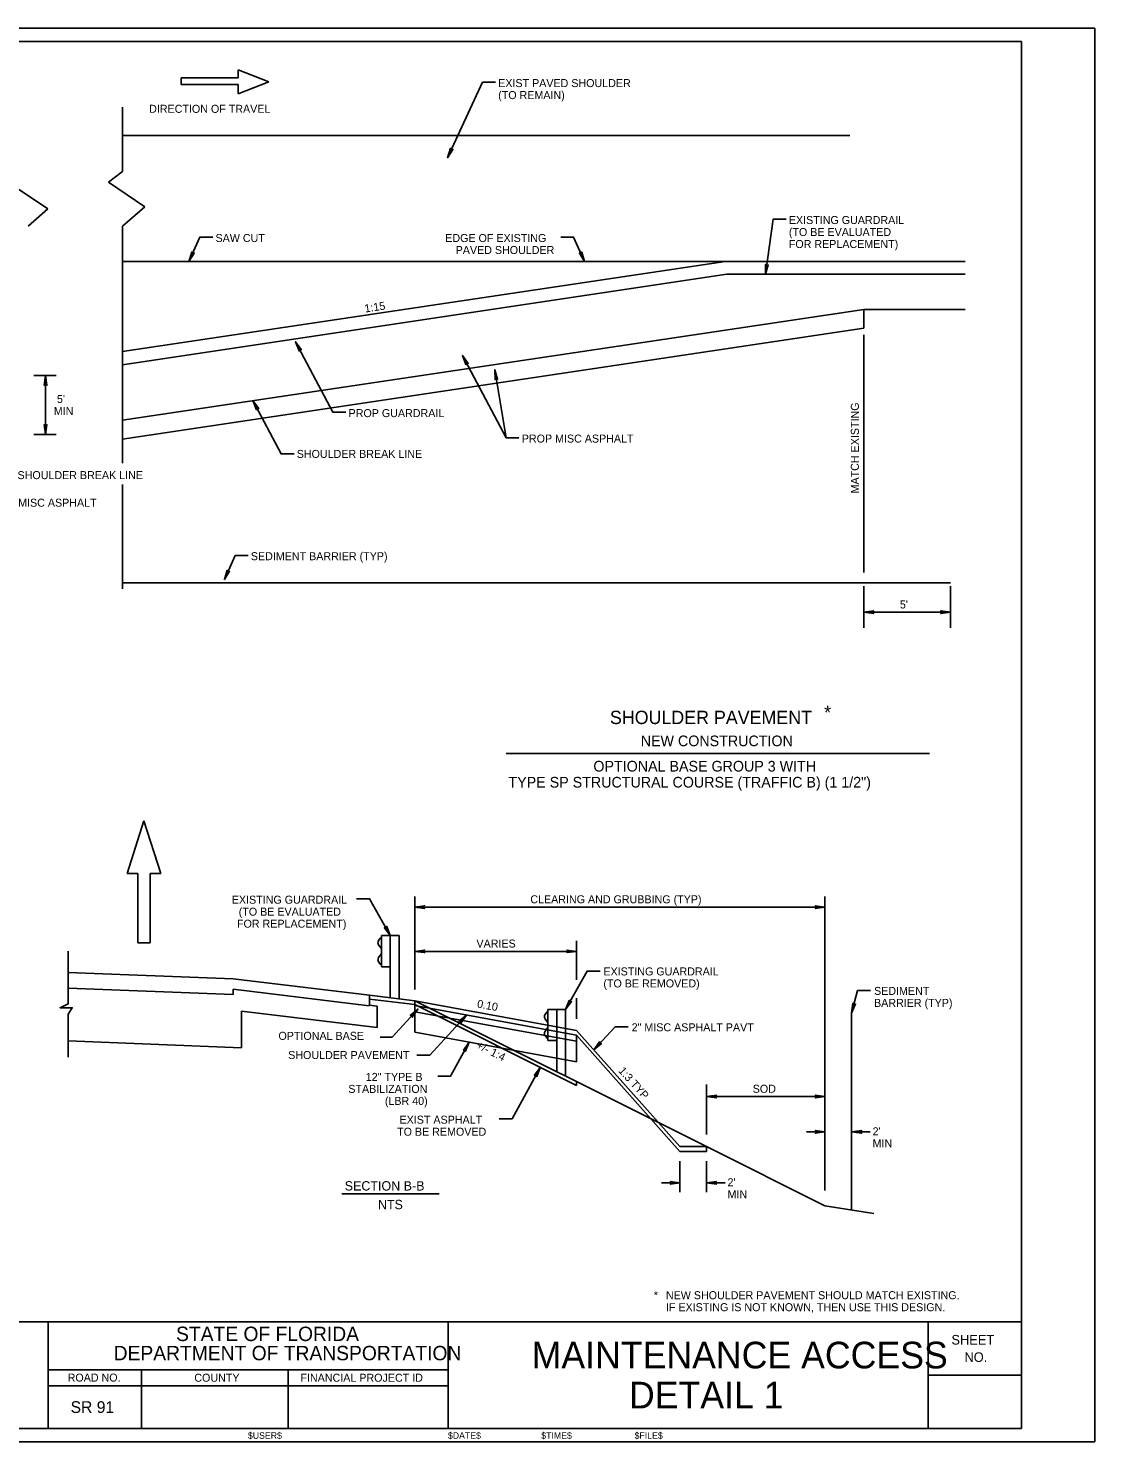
# Model space of a CAD drawing. Extents: x 96794 to 96959, y 32203 to 32309.
# Drawn here: x 96878.8 to 96958.8, y 32202.6 to 32308.6 of the extents above; entities that cross this region are included whole.
import ezdxf

# ---------------------------------------------------------------- set-up
doc = ezdxf.new("R2010")
doc.units = 0
for name, color, linetype in [('AsphaltMisc', 7, 'Continuous'), ('Base_ex', 7, 'Continuous'), ('BreakLine_dp', 7, 'Continuous'), ('DimLines_dp', 7, 'Continuous'), ('EOP', 7, 'Continuous'), ('GuardrailRt', 7, 'Continuous'), ('LeaderLine_dp', 7, 'Continuous'), ('Miscellaneous2', 7, 'Continuous'), ('PavtAsph_ep', 7, 'Continuous'), ('PlotBorder_dp', 7, 'Continuous'), ('SawCuts', 7, 'Continuous'), ('SheetBorder_dp', 7, 'Continuous'), ('SheetLines_dp', 7, 'Continuous'), ('SheetLinesMisc2_dp', 7, 'Continuous'), ('SiltFence', 7, 'Continuous'), ('Slopes_px', 7, 'Continuous'), ('TextMinor', 7, 'Continuous'), ('TextMisc', 7, 'Continuous'), ('TextTitle', 7, 'Continuous'), ('XSTypical_px', 7, 'Continuous')]:
    doc.layers.add(name, color=color, linetype=linetype)

msp = doc.modelspace()

# ---------------------------------------------------------------- linework, layer by layer
at = {"layer": 'AsphaltMisc'}
for p, q in [((96885.88, 32284.31), (96931.08, 32291.06)), ((96885.88, 32284.31), (96931.08, 32291.06)), ((96931.08, 32291.06), (96885.88, 32291.06)), ((96885.88, 32291.06), (96885.88, 32284.31)), ((96931.08, 32291.06), (96949.08, 32291.06)), ((96885.88, 32279.15), (96941.49, 32287.46)), ((96941.49, 32287.46), (96949.08, 32287.46))]:
    msp.add_line(p, q, dxfattribs=at)
at = {"layer": 'Base_ex'}
for p, q in [((96904.99, 32233.62), (96894.81, 32234.85)), ((96894.81, 32232.09), (96894.81, 32234.85)), ((96904.4, 32235.28), (96904.99, 32235.21)), ((96904.99, 32235.21), (96904.99, 32233.62)), ((96881.82, 32232.61), (96894.81, 32232.09))]:
    msp.add_line(p, q, dxfattribs=at)
at = {"layer": 'BreakLine_dp'}
msp.add_lwpolyline([(96881.82, 32239.35), (96881.82, 32235.4), (96881.2, 32235.1), (96882.12, 32235.1), (96881.81, 32234.61), (96881.81, 32231.4)], dxfattribs=at)
at = {"layer": 'DimLines_dp'}
for p, q in [((96885.88, 32302.63), (96885.88, 32297.81)), ((96884.83, 32297), (96885.88, 32297.81)), ((96880.29, 32295), (96877.56, 32296.84)), ((96887.56, 32295.16), (96884.83, 32297)), ((96885.88, 32293.7), (96887.56, 32295.16)), ((96878.82, 32293.72), (96880.29, 32295)), ((96885.88, 32293.7), (96885.88, 32275.94)), ((96941.49, 32267.74), (96941.49, 32285.55)), ((96879.24, 32282.51), (96880.92, 32282.51)), ((96880.12, 32282.51), (96880.12, 32278.09)), ((96879.24, 32278.09), (96880.92, 32278.09)), ((96885.88, 32274.34), (96885.88, 32266.52)), ((96941.49, 32263.58), (96941.49, 32266.7)), ((96947.98, 32263.58), (96947.98, 32266.7)), ((96947.98, 32264.76), (96941.49, 32264.76)), ((96907.81, 32236.47), (96907.81, 32243.45)), ((96938.57, 32221.4), (96938.57, 32243.45)), ((96907.81, 32242.65), (96938.57, 32242.65)), ((96919.94, 32237.19), (96919.94, 32240.12)), ((96907.81, 32239.32), (96919.94, 32239.32)), ((96919.94, 32234.26), (96919.94, 32235.82)), ((96929.69, 32225.59), (96929.69, 32229.33)), ((96929.69, 32228.44), (96938.57, 32228.44)), ((96937.18, 32225.79), (96938.57, 32225.79)), ((96937.18, 32225.79), (96938.57, 32225.79)), ((96941.97, 32225.79), (96940.57, 32225.79)), ((96941.97, 32225.79), (96940.57, 32225.79)), ((96927.69, 32221.26), (96927.69, 32223.58)), ((96929.69, 32221.26), (96929.69, 32223.58)), ((96926.3, 32221.97), (96927.69, 32221.97)), ((96926.3, 32221.97), (96927.69, 32221.97)), ((96931.09, 32221.97), (96929.69, 32221.97)), ((96931.09, 32221.97), (96929.69, 32221.97)), ((96902.34, 32221.14), (96909.64, 32221.14))]:
    msp.add_line(p, q, dxfattribs=at)
for points in [[(96880.12, 32281.98), (96880.21, 32281.78), (96880.12, 32282.51), (96880.02, 32281.78), (96880.12, 32281.98)], [(96880.12, 32278.62), (96880.21, 32278.83), (96880.12, 32278.09), (96880.02, 32278.83), (96880.12, 32278.62)], [(96942.02, 32264.76), (96942.23, 32264.86), (96941.49, 32264.76), (96942.23, 32264.66), (96942.02, 32264.76)], [(96947.45, 32264.76), (96947.25, 32264.86), (96947.98, 32264.76), (96947.25, 32264.66), (96947.45, 32264.76)], [(96908.34, 32242.65), (96908.54, 32242.55), (96907.81, 32242.65), (96908.54, 32242.75), (96908.34, 32242.65)], [(96938.04, 32242.65), (96937.84, 32242.75), (96938.57, 32242.65), (96937.84, 32242.55), (96938.04, 32242.65)], [(96908.34, 32239.32), (96908.54, 32239.42), (96907.81, 32239.32), (96908.54, 32239.23), (96908.34, 32239.32)], [(96919.41, 32239.32), (96919.21, 32239.42), (96919.94, 32239.32), (96919.21, 32239.23), (96919.41, 32239.32)], [(96930.22, 32228.44), (96930.43, 32228.53), (96929.69, 32228.44), (96930.43, 32228.34), (96930.22, 32228.44)], [(96938.04, 32228.44), (96937.84, 32228.53), (96938.57, 32228.44), (96937.84, 32228.34), (96938.04, 32228.44)], [(96938.04, 32225.79), (96937.84, 32225.69), (96938.57, 32225.79), (96937.84, 32225.88), (96938.04, 32225.79)], [(96938.04, 32225.79), (96937.84, 32225.88), (96938.57, 32225.79), (96937.84, 32225.69), (96938.04, 32225.79)], [(96941.1, 32225.79), (96941.31, 32225.69), (96940.57, 32225.79), (96941.31, 32225.88), (96941.1, 32225.79)], [(96941.1, 32225.79), (96941.31, 32225.88), (96940.57, 32225.79), (96941.31, 32225.69), (96941.1, 32225.79)], [(96927.16, 32221.97), (96926.96, 32221.87), (96927.69, 32221.97), (96926.96, 32222.06), (96927.16, 32221.97)], [(96927.16, 32221.97), (96926.96, 32222.06), (96927.69, 32221.97), (96926.96, 32221.87), (96927.16, 32221.97)], [(96930.22, 32221.97), (96930.43, 32221.87), (96929.69, 32221.97), (96930.43, 32222.06), (96930.22, 32221.97)], [(96930.22, 32221.97), (96930.43, 32222.06), (96929.69, 32221.97), (96930.43, 32221.87), (96930.22, 32221.97)]]:
    msp.add_lwpolyline(points, dxfattribs=at)
at = {"layer": 'EOP'}
for p, q in [((96890.28, 32304.83), (96894.57, 32304.83)), ((96890.28, 32304.83), (96890.28, 32304.33)), ((96894.57, 32304.83), (96894.57, 32305.44)), ((96894.57, 32305.44), (96896.87, 32304.54)), ((96894.57, 32304.33), (96890.28, 32304.33)), ((96894.57, 32303.64), (96896.87, 32304.54)), ((96894.57, 32303.64), (96894.57, 32304.33)), ((96885.88, 32300.52), (96940.43, 32300.52))]:
    msp.add_line(p, q, dxfattribs=at)
at = {"layer": 'GuardrailRt'}
for p, q in [((96885.88, 32283.32), (96931.22, 32290.1)), ((96931.22, 32290.1), (96949.08, 32290.1))]:
    msp.add_line(p, q, dxfattribs=at)
at = {"layer": 'LeaderLine_dp'}
for points in [[(96913.86, 32304.5), (96912.89, 32304.5), (96910.26, 32298.84)], [(96910.48, 32299.32), (96910.48, 32299.55), (96910.26, 32298.84), (96910.66, 32299.46), (96910.48, 32299.32)], [(96935.66, 32294.24), (96934.69, 32294.24), (96934.12, 32290.1)], [(96892.65, 32292.89), (96891.69, 32292.89), (96890.87, 32291.06)], [(96918.76, 32292.89), (96919.72, 32292.89), (96920.54, 32291.06)], [(96891.09, 32291.55), (96891.08, 32291.77), (96890.87, 32291.06), (96891.26, 32291.69), (96891.09, 32291.55)], [(96920.32, 32291.55), (96920.33, 32291.77), (96920.54, 32291.06), (96920.15, 32291.69), (96920.32, 32291.55)], [(96934.19, 32290.63), (96934.12, 32290.84), (96934.12, 32290.1), (96934.31, 32290.81), (96934.19, 32290.63)], [(96902.64, 32279.75), (96901.67, 32279.75), (96898.87, 32285.04)], [(96899.12, 32284.57), (96899.3, 32284.44), (96898.87, 32285.04), (96899.13, 32284.35), (96899.12, 32284.57)], [(96915.62, 32277.84), (96914.66, 32277.84), (96911.38, 32284.02)], [(96911.63, 32283.55), (96911.81, 32283.42), (96911.38, 32284.02), (96911.64, 32283.33), (96911.63, 32283.55)], [(96915.62, 32277.84), (96914.66, 32277.84), (96913.8, 32282.94)], [(96913.89, 32282.42), (96914.02, 32282.23), (96913.8, 32282.94), (96913.83, 32282.2), (96913.89, 32282.42)], [(96898.75, 32276.63), (96897.78, 32276.63), (96895.67, 32280.63)], [(96895.92, 32280.16), (96896.1, 32280.03), (96895.67, 32280.63), (96895.93, 32279.94), (96895.92, 32280.16)], [(96895.31, 32269.02), (96894.34, 32269.02), (96893.53, 32267.2)], [(96893.74, 32267.68), (96893.74, 32267.91), (96893.53, 32267.2), (96893.91, 32267.83), (96893.74, 32267.68)], [(96903.44, 32243.26), (96904.41, 32243.26), (96905.97, 32240.51)], [(96905.71, 32240.97), (96905.7, 32241.19), (96905.97, 32240.51), (96905.53, 32241.1), (96905.71, 32240.97)], [(96921.7, 32237.85), (96920.73, 32237.85), (96919.12, 32234.96)], [(96941.99, 32236.38), (96941.02, 32236.38), (96940.57, 32234.7)], [(96905.2, 32232.89), (96906.1, 32232.89), (96908.04, 32235)], [(96907.68, 32234.61), (96907.47, 32234.52), (96908.04, 32235), (96907.61, 32234.39), (96907.68, 32234.61)], [(96919.38, 32235.43), (96919.39, 32235.65), (96919.12, 32234.96), (96919.56, 32235.56), (96919.38, 32235.43)], [(96940.71, 32235.22), (96940.67, 32235.44), (96940.57, 32234.7), (96940.86, 32235.39), (96940.71, 32235.22)], [(96907.97, 32231.55), (96908.94, 32231.55), (96911.69, 32234.55)], [(96911.33, 32234.16), (96911.12, 32234.08), (96911.69, 32234.55), (96911.27, 32233.95), (96911.33, 32234.16)], [(96923.81, 32233.66), (96922.84, 32233.66), (96921.23, 32231.95)], [(96909.53, 32229.97), (96910.49, 32229.97), (96911.89, 32232.52)], [(96911.64, 32232.05), (96911.45, 32231.92), (96911.89, 32232.52), (96911.62, 32231.83), (96911.64, 32232.05)], [(96921.59, 32232.34), (96921.66, 32232.55), (96921.23, 32231.95), (96921.8, 32232.42), (96921.59, 32232.34)], [(96914.13, 32226.77), (96915.1, 32226.77), (96917.22, 32230.62)], [(96916.96, 32230.16), (96916.78, 32230.03), (96917.22, 32230.62), (96916.95, 32229.94), (96916.96, 32230.16)]]:
    msp.add_lwpolyline(points, dxfattribs=at)
at = {"layer": 'Miscellaneous2'}
msp.add_line((96940.57, 32219.93), (96940.57, 32234.7), dxfattribs=at)
at = {"layer": 'PavtAsph_ep'}
for p, q in [((96887.49, 32249.11), (96886.24, 32245.16)), ((96888.75, 32245.16), (96887.49, 32249.11)), ((96887.03, 32245.16), (96886.24, 32245.16)), ((96887.03, 32245.16), (96887.03, 32239.96)), ((96887.96, 32245.16), (96888.75, 32245.16)), ((96887.96, 32239.96), (96887.96, 32245.16)), ((96887.03, 32239.96), (96887.96, 32239.96)), ((96905.07, 32240.1), (96905.22, 32240.31)), ((96905.31, 32240.36), (96905.23, 32240.32)), ((96905.31, 32238.17), (96905.31, 32240.51)), ((96905.31, 32240.51), (96906.64, 32240.51)), ((96905.97, 32235.84), (96905.97, 32240.51)), ((96906.64, 32235.76), (96906.64, 32240.51)), ((96905.07, 32239.85), (96905.28, 32239.56)), ((96905.07, 32238.83), (96905.28, 32239.12)), ((96905.07, 32238.58), (96905.22, 32238.37)), ((96905.31, 32238.32), (96905.23, 32238.36)), ((96905.97, 32238.17), (96905.31, 32238.17)), ((96881.82, 32237.75), (96894.19, 32237.26)), ((96904.4, 32236.03), (96894.19, 32237.26)), ((96881.82, 32236.57), (96894.19, 32236.08)), ((96894.19, 32236.08), (96894.19, 32236.48)), ((96894.19, 32236.48), (96904.39, 32235.25)), ((96904.4, 32235.25), (96904.4, 32236.03)), ((96904.4, 32236.03), (96907.81, 32235.62)), ((96907.81, 32235.33), (96904.4, 32235.74)), ((96907.81, 32235.62), (96929.69, 32224.68)), ((96907.81, 32235.33), (96919.94, 32229.26)), ((96917.55, 32234.56), (96917.7, 32234.76)), ((96917.79, 32234.82), (96917.71, 32234.77)), ((96917.79, 32232.63), (96917.79, 32234.96)), ((96917.79, 32234.96), (96919.12, 32234.96)), ((96918.45, 32230.3), (96918.45, 32234.96)), ((96919.12, 32229.96), (96919.12, 32234.96)), ((96917.55, 32234.3), (96917.76, 32234.02)), ((96917.55, 32233.29), (96917.76, 32233.58)), ((96917.55, 32233.03), (96917.7, 32232.83)), ((96917.79, 32232.78), (96917.71, 32232.82)), ((96918.45, 32232.63), (96917.79, 32232.63)), ((96919.94, 32229.55), (96919.94, 32229.26)), ((96929.69, 32224.68), (96938.57, 32220.24)), ((96938.57, 32220.24), (96942.24, 32219.67))]:
    msp.add_line(p, q, dxfattribs=at)
for centre, major_axis, start_param, end_param in [((96905.12, 32239.97), (0, 0.156), 0.622533, 2.519059), ((96905.24, 32240.26), (0, 0.0625), 0.266062, 0.622534), ((96905.23, 32239.43), (0, 0.156), 4.712389, 5.660655), ((96905.23, 32239.25), (0, 0.156), 3.764123, 4.712389), ((96905.12, 32238.7), (0, 0.156), 0.622533, 2.519059), ((96905.24, 32238.42), (0, -0.0625), 5.660652, 6.017123), ((96917.72, 32234.71), (0, 0.0625), 0.266062, 0.622534), ((96917.6, 32234.43), (0, 0.156), 0.622533, 2.519059), ((96917.71, 32233.89), (0, 0.156), 4.712389, 5.660655), ((96917.71, 32233.7), (0, 0.156), 3.764123, 4.712389), ((96917.6, 32233.16), (0, 0.156), 0.622533, 2.519059), ((96917.72, 32232.88), (0, -0.0625), 5.660652, 6.017123)]:
    msp.add_ellipse(centre, major_axis=major_axis, ratio=0.5, start_param=start_param, end_param=end_param, dxfattribs=at)
at = {"layer": 'PlotBorder_dp'}
msp.add_lwpolyline([(96793.8, 32202.55), (96958.8, 32202.55), (96958.8, 32308.55), (96793.8, 32308.55)], close=True, dxfattribs=at)
at = {"layer": 'SawCuts'}
msp.add_line((96885.88, 32291.06), (96931.08, 32291.06), dxfattribs=at)
at = {"layer": 'SheetBorder_dp'}
for p, q in [((96799.3, 32307.55), (96953.3, 32307.55)), ((96953.3, 32307.55), (96953.3, 32203.55)), ((96799.3, 32211.55), (96953.3, 32211.55)), ((96799.3, 32203.55), (96953.3, 32203.55))]:
    msp.add_line(p, q, dxfattribs=at)
at = {"layer": 'SheetLines_dp'}
for p, q in [((96880.3, 32211.55), (96880.3, 32203.55)), ((96910.3, 32203.55), (96910.3, 32211.55)), ((96946.3, 32203.55), (96946.3, 32211.55)), ((96880.3, 32207.95), (96910.3, 32207.95)), ((96887.3, 32207.95), (96887.3, 32203.55)), ((96898.3, 32207.95), (96898.3, 32203.55)), ((96946.3, 32207.55), (96953.3, 32207.55)), ((96880.3, 32206.75), (96910.3, 32206.75))]:
    msp.add_line(p, q, dxfattribs=at)
at = {"layer": 'SheetLinesMisc2_dp'}
msp.add_line((96914.65, 32254.17), (96946.42, 32254.17), dxfattribs=at)
at = {"layer": 'SiltFence'}
msp.add_line((96947.98, 32266.97), (96885.88, 32266.97), dxfattribs=at)
at = {"layer": 'Slopes_px'}
for p, q in [((96941.49, 32287.48), (96941.49, 32286.07)), ((96885.88, 32277.73), (96941.49, 32286.05))]:
    msp.add_line(p, q, dxfattribs=at)
at = {"layer": 'XSTypical_px'}
for p, q in [((96907.81, 32235.62), (96907.81, 32233.26)), ((96919.94, 32233.4), (96907.81, 32235.62)), ((96907.81, 32235.26), (96919.94, 32233.04)), ((96919.94, 32232.59), (96907.81, 32234.8)), ((96907.81, 32234.8), (96907.81, 32233.26)), ((96907.81, 32233.26), (96919.94, 32231.04)), ((96919.94, 32233.4), (96927.69, 32224.68)), ((96927.69, 32224.68), (96919.94, 32233.4)), ((96919.94, 32233.04), (96919.94, 32231.04)), ((96919.94, 32233.04), (96927.69, 32224.32)), ((96919.94, 32233.04), (96927.69, 32224.32)), ((96919.94, 32231.04), (96919.94, 32232.59)), ((96927.69, 32224.68), (96929.69, 32224.68)), ((96929.69, 32224.68), (96927.69, 32224.68)), ((96927.69, 32224.32), (96929.69, 32224.32)), ((96927.69, 32224.32), (96929.69, 32224.32)), ((96929.69, 32224.68), (96929.69, 32224.32)), ((96929.69, 32224.32), (96929.69, 32224.68))]:
    msp.add_line(p, q, dxfattribs=at)
for points in [[(96907.81, 32235.62), (96919.94, 32233.4)], [(96907.81, 32235.62), (96907.81, 32235.33), (96907.81, 32235.26)], [(96919.94, 32233.04), (96907.81, 32235.26)], [(96907.81, 32233.26), (96919.94, 32231.04)]]:
    msp.add_lwpolyline(points, dxfattribs=at)

# ---------------------------------------------------------------- texts
at = {"layer": 'DimLines_dp'}
for s, p in [('SECTION B-B', (96902.55, 32221.39)), ('NTS', (96905.04, 32219.99))]:
    msp.add_text(s, height=0.7, dxfattribs=at).set_placement(p)
at = {"layer": 'TextMinor'}
for s, p in [('$USER$', (96895.29, 32202.77)), ('$DATE$', (96910.29, 32202.77)), ('$TIME$', (96917.29, 32202.77)), ('$FILE$', (96924.29, 32202.77))]:
    msp.add_text(s, height=0.49, dxfattribs=at).set_placement(p)
at = {"layer": 'TextMisc'}
for s, height, p in [('EXIST PAVED SHOULDER', 0.6, (96914.06, 32304.14)), ('(TO REMAIN)', 0.6, (96914.06, 32303.24)), ('DIRECTION OF TRAVEL', 0.6, (96887.88, 32302.21)), ('EXISTING GUARDRAIL', 0.6, (96935.86, 32293.87)), ('SAW CUT', 0.6, (96892.86, 32292.52)), ('EDGE OF EXISTING', 0.6, (96910.09, 32292.52)), ('(TO BE EVALUATED', 0.6, (96935.86, 32292.97)), ('PAVED SHOULDER', 0.6, (96910.87, 32291.62)), ('FOR REPLACEMENT)', 0.6, (96935.86, 32292.07)), ("5'", 0.6, (96880.97, 32280.45)), ('MIN', 0.6, (96880.73, 32279.55)), ('PROP GUARDRAIL', 0.6, (96902.84, 32279.39)), ('PROP MISC ASPHALT', 0.6, (96915.83, 32277.48)), ('SHOULDER BREAK LINE', 0.6, (96898.95, 32276.33)), ('SHOULDER BREAK LINE', 0.6, (96878.01, 32274.74)), ('PROP MISC ASPHALT', 0.6, (96875.56, 32272.67)), ('SEDIMENT BARRIER (TYP)', 0.6, (96895.51, 32268.66)), ("5'", 0.6, (96944.19, 32265.04)), ('OPTIONAL BASE GROUP 3 WITH', 0.8, (96921.2, 32252.81)), ('TYPE SP STRUCTURAL COURSE (TRAFFIC B) (1 1/2")', 0.8, (96914.83, 32251.61)), ('EXISTING GUARDRAIL', 0.6, (96894.08, 32242.9)), ('CLEARING AND GRUBBING (TYP)', 0.6, (96916.47, 32242.93)), ('(TO BE EVALUATED', 0.6, (96894.6, 32242)), ('FOR REPLACEMENT)', 0.6, (96894.47, 32241.1)), ('VARIES', 0.6, (96912.43, 32239.61)), ('EXISTING GUARDRAIL', 0.6, (96921.95, 32237.52)), ('(TO BE REMOVED)', 0.6, (96921.95, 32236.62)), ('SEDIMENT', 0.6, (96942.25, 32236.06)), ('BARRIER (TYP)', 0.6, (96942.25, 32235.16)), ('2" MISC ASPHALT PAVT', 0.6, (96924.07, 32233.33)), ('OPTIONAL BASE', 0.6, (96897.58, 32232.69)), ('SHOULDER PAVEMENT', 0.6, (96898.31, 32231.25)), ('STABILIZATION', 0.6, (96902.82, 32228.71)), ('12" TYPE B', 0.6, (96904.13, 32229.61)), ('SOD', 0.6, (96933.15, 32228.72)), ('(LBR 40)', 0.6, (96905.56, 32227.81)), ('EXIST ASPHALT', 0.6, (96906.66, 32226.4)), ("2'", 0.6, (96942.14, 32225.53)), ('TO BE REMOVED', 0.6, (96906.48, 32225.5)), ('MIN', 0.6, (96942.14, 32224.63)), ("2'", 0.6, (96931.26, 32221.71)), ('MIN', 0.6, (96931.26, 32220.81)), ('*', 0.6, (96925.73, 32213.24)), ('NEW SHOULDER PAVEMENT SHOULD MATCH EXISTING.', 0.6, (96926.64, 32213.24)), ('IF EXISTING IS NOT KNOWN, THEN USE THIS DESIGN.', 0.6, (96926.64, 32212.34)), ('STATE OF FLORIDA', 1.08, (96889.9, 32210.1)), ('DEPARTMENT OF TRANSPORTATION', 1.08, (96885.22, 32208.66)), ('MAINTENANCE ACCESS', 2, (96916.57, 32208.05)), ('ROAD NO.', 0.6, (96881.77, 32207.06)), ('COUNTY', 0.6, (96891.27, 32207.05)), ('FINANCIAL PROJECT ID', 0.6, (96899.23, 32207.05)), ('DETAIL 1', 2, (96923.87, 32205.05)), ('SR 91', 0.88, (96881.99, 32204.71))]:
    msp.add_text(s, height=height, dxfattribs=at).set_placement(p)
for s, height, rotation, p in [('1:15', 0.6, 8.5028, (96904.08, 32287.23)), ('MATCH EXISTING', 0.6, 90, (96941.11, 32273.67)), ('0.10', 0.6, 349.6377, (96912.44, 32235.12)), ('+/- 1:4', 0.6, 333.4393, (96912.36, 32232.09)), ('1:3 TYP', 0.6, 311.6333, (96923.04, 32230.34)), ('SHEET', 0.72, 359.8607, (96948.05, 32209.84)), ('NO.', 0.72, 359.8607, (96949.03, 32208.54))]:
    msp.add_text(s, height=height, rotation=rotation, dxfattribs=at).set_placement(p)
at = {"layer": 'TextTitle'}
for s, height, p in [('SHOULDER PAVEMENT', 1, (96922.44, 32256.37)), ('*', 1, (96938.51, 32256.74)), ('NEW CONSTRUCTION', 0.8, (96924.75, 32254.71))]:
    msp.add_text(s, height=height, dxfattribs=at).set_placement(p)

doc.saveas('drawing.dxf')
